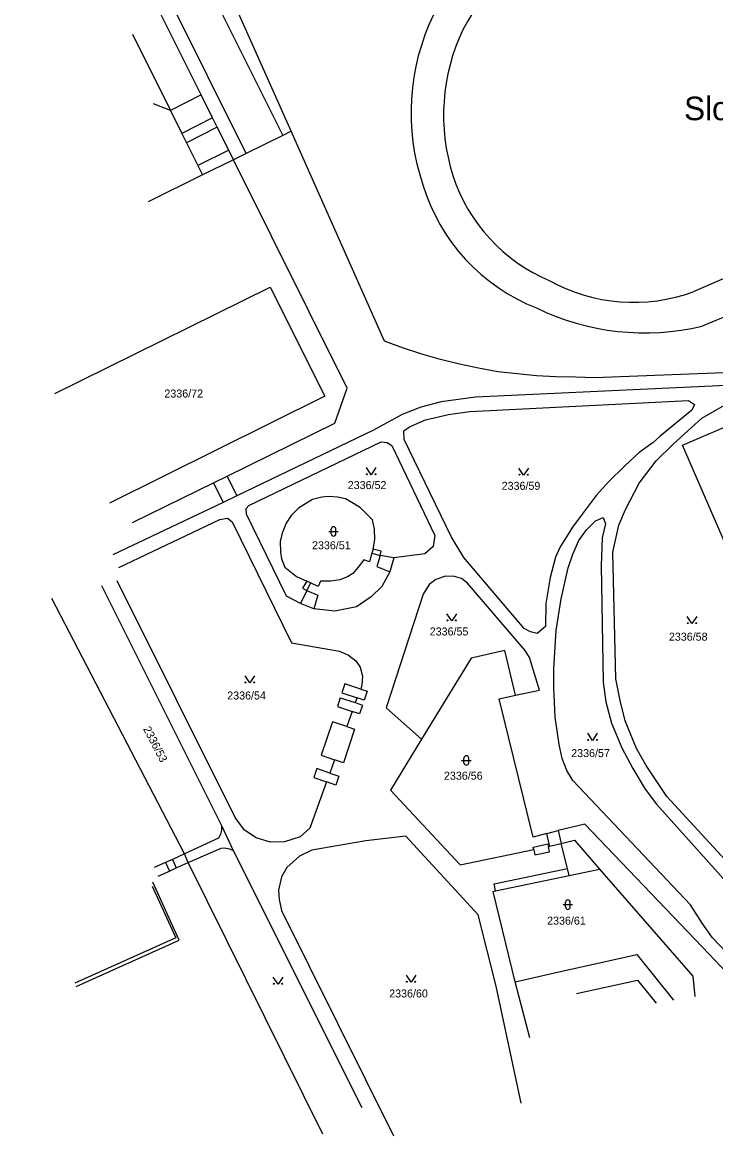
# Model space of a CAD drawing. Extents: x -822293 to -820259, y -1071573 to -1068794.
# Drawn here: x -821067.6 to -820920.3, y -1071364.1 to -1071127.6 of the extents above; entities that cross this region are included whole.
import ezdxf

# ---------------------------------------------------------------- set-up
doc = ezdxf.new("R2010")
doc.units = 0
for name, color, linetype in [('Vrstva 1', 7, 'Continuous'), ('Vrstva 15', 7, 'Continuous'), ('Vrstva 18', 7, 'Continuous'), ('Vrstva 2', 7, 'Continuous'), ('Vrstva 25', 7, 'Continuous'), ('Vrstva 3', 7, 'Continuous'), ('Vrstva 4', 7, 'Continuous')]:
    doc.layers.add(name, color=color, linetype=linetype)

msp = doc.modelspace()

# ---------------------------------------------------------------- linework, layer by layer
at = {"layer": 'Vrstva 1'}
for p, q in [((-821010.48, -1071150.74), (-821030.29, -1071106.24)), ((-821027.17, -1071147.89), (-821029.61, -1071142.98)), ((-821036.15, -1071146.31), (-821033.7, -1071151.22)), ((-821026.2, -1071149.83), (-821027.17, -1071147.89)), ((-821033.7, -1071151.22), (-821032.73, -1071153.16)), ((-821023.75, -1071154.75), (-821026.2, -1071149.83)), ((-821010.48, -1071150.74), (-821012.25, -1071151.61)), ((-820990.69, -1071195.3), (-821010.48, -1071150.74)), ((-821032.73, -1071153.16), (-821030.29, -1071158.03)), ((-821012.25, -1071151.61), (-821020.06, -1071155.46)), ((-821022.74, -1071156.78), (-821023.75, -1071154.75)), ((-821020.06, -1071155.46), (-821022.74, -1071156.78)), ((-821030.29, -1071158.03), (-821029.31, -1071159.98)), ((-821022.74, -1071156.78), (-821029.31, -1071159.98)), ((-820998.6, -1071205.31), (-821022.74, -1071156.78)), ((-821029.31, -1071159.98), (-821040.85, -1071165.71)), ((-821060.69, -1071206.47), (-821014.96, -1071183.85)), ((-821014.96, -1071183.85), (-821003.34, -1071207)), ((-820986.66, -1071196.78), (-820990.69, -1071195.3)), ((-820982.74, -1071198.06), (-820986.66, -1071196.78)), ((-820978.79, -1071199.23), (-820982.74, -1071198.06)), ((-820974.75, -1071200.18), (-820978.79, -1071199.23)), ((-820970.69, -1071201.05), (-820974.75, -1071200.18)), ((-820966.6, -1071201.83), (-820970.69, -1071201.05)), ((-820962.51, -1071202.26), (-820966.6, -1071201.83)), ((-820958.4, -1071202.67), (-820962.51, -1071202.26)), ((-820954.29, -1071202.91), (-820958.4, -1071202.67)), ((-820950.12, -1071203), (-820954.29, -1071202.91)), ((-820946, -1071203.12), (-820950.12, -1071203)), ((-820891.98, -1071201.01), (-820946, -1071203.12)), ((-821001.19, -1071212.77), (-820998.6, -1071205.31)), ((-820893.3, -1071203.6), (-820971.32, -1071207.19)), ((-821003.34, -1071207), (-821049.09, -1071229.74)), ((-820971.32, -1071207.19), (-820978.65, -1071208.22)), ((-820972.51, -1071210.23), (-820926.1, -1071207.9)), ((-820926.1, -1071207.9), (-820924.8, -1071208.8)), ((-820982.97, -1071209.31), (-820986.89, -1071210.89)), ((-820978.65, -1071208.22), (-820982.97, -1071209.31)), ((-820977.04, -1071210.93), (-820972.51, -1071210.23)), ((-820925.4, -1071210), (-820932.1, -1071215.5)), ((-820927.37, -1071217.43), (-820906.4, -1071208.35)), ((-820924.8, -1071208.8), (-820925.4, -1071210)), ((-820923.27, -1071211.68), (-820918.45, -1071208.9)), ((-820986.89, -1071210.89), (-820993.03, -1071214.25)), ((-820985.32, -1071213.51), (-820981.93, -1071212.04)), ((-820981.93, -1071212.04), (-820977.04, -1071210.93)), ((-820929.38, -1071217.23), (-820923.27, -1071211.68)), ((-821024.08, -1071223.99), (-821001.19, -1071212.77)), ((-820993.03, -1071214.25), (-821022.02, -1071228.2)), ((-820986.55, -1071214.4), (-820985.32, -1071213.51)), ((-820986.47, -1071216.23), (-820986.55, -1071214.4)), ((-821019.48, -1071230.25), (-820991.39, -1071216.7)), ((-820991.39, -1071216.7), (-820990.11, -1071216.85)), ((-820990.11, -1071216.85), (-820989.11, -1071217.48)), ((-820976.48, -1071236.8), (-820986.47, -1071216.23)), ((-820933.59, -1071216.82), (-820936.55, -1071218.99)), ((-820932.1, -1071215.5), (-820933.59, -1071216.82)), ((-820932.95, -1071220.72), (-820929.38, -1071217.23)), ((-820903.02, -1071273.66), (-820927.37, -1071217.43)), ((-820989.11, -1071217.48), (-820980, -1071236.62)), ((-820936.55, -1071218.99), (-820939.61, -1071221.78)), ((-820939.61, -1071221.78), (-820943.1, -1071225.2)), ((-820936.6, -1071225.5), (-820932.95, -1071220.72)), ((-821027.01, -1071225.42), (-821024.08, -1071223.99)), ((-821044.19, -1071233.84), (-821027.01, -1071225.42)), ((-820943.1, -1071225.2), (-820945.67, -1071228.1)), ((-820939.5, -1071231.1), (-820936.6, -1071225.5)), ((-821022.02, -1071228.2), (-821024.94, -1071229.6)), ((-821005.93, -1071228.96), (-821007.22, -1071229.71)), ((-821003.99, -1071228.43), (-821005.93, -1071228.96)), ((-821002.57, -1071228.31), (-821003.99, -1071228.43)), ((-821000.67, -1071228.43), (-821002.57, -1071228.31)), ((-820998.93, -1071228.84), (-821000.67, -1071228.43)), ((-820997.23, -1071229.8), (-820998.93, -1071228.84)), ((-820945.67, -1071228.1), (-820948.68, -1071232.05)), ((-821024.94, -1071229.6), (-821048.33, -1071240.68)), ((-821020.06, -1071230.89), (-821019.48, -1071230.25)), ((-821019.99, -1071232.04), (-821020.06, -1071230.89)), ((-821008.91, -1071230.82), (-821010.5, -1071232.37)), ((-821007.22, -1071229.71), (-821008.91, -1071230.82)), ((-820995.76, -1071230.71), (-820997.23, -1071229.8)), ((-820994.37, -1071232.11), (-820995.76, -1071230.71)), ((-820940.87, -1071234.4), (-820939.5, -1071231.1)), ((-821047.08, -1071243.43), (-821025.63, -1071233.18)), ((-821025.63, -1071233.18), (-821024.03, -1071232.92)), ((-821024.03, -1071232.92), (-821023, -1071233.73)), ((-821023, -1071233.73), (-821010.44, -1071259.43)), ((-821011.5, -1071249.52), (-821019.99, -1071232.04)), ((-821011.57, -1071233.97), (-821012.37, -1071236.1)), ((-821010.5, -1071232.37), (-821011.57, -1071233.97)), ((-820993.22, -1071233.29), (-820994.37, -1071232.11)), ((-820992.81, -1071235.26), (-820993.22, -1071233.29)), ((-820948.68, -1071232.05), (-820950.75, -1071234.85)), ((-820947.76, -1071235.4), (-820945.88, -1071233.47)), ((-820945.88, -1071233.47), (-820944.25, -1071232.75)), ((-820944.25, -1071232.75), (-820943.69, -1071234.12)), ((-821012.37, -1071236.1), (-821012.84, -1071237.91)), ((-820992.69, -1071237.45), (-820992.81, -1071235.26)), ((-820950.75, -1071234.85), (-820953.44, -1071239.13)), ((-820949.39, -1071237.7), (-820947.76, -1071235.4)), ((-820943.69, -1071234.12), (-820944.41, -1071237.11)), ((-820942.16, -1071240.13), (-820940.87, -1071234.4)), ((-821012.84, -1071237.91), (-821012.75, -1071240.11)), ((-820993.1, -1071239.54), (-820992.69, -1071237.45)), ((-820980, -1071236.62), (-820980.36, -1071238.92)), ((-820973.8, -1071241.31), (-820976.48, -1071236.8)), ((-820950.64, -1071240.6), (-820949.39, -1071237.7)), ((-820944.41, -1071237.11), (-820944.65, -1071242.99)), ((-821012.75, -1071240.11), (-821012.51, -1071241.55)), ((-820991.36, -1071239.9), (-820993.1, -1071239.54)), ((-820991.57, -1071240.87), (-820991.36, -1071239.9)), ((-820988.69, -1071241.36), (-820991.57, -1071240.87)), ((-820982.07, -1071240.49), (-820988.69, -1071241.36)), ((-820980.36, -1071238.92), (-820982.07, -1071240.49)), ((-820953.44, -1071239.13), (-820954.33, -1071241.2)), ((-820951.63, -1071243.47), (-820950.64, -1071240.6)), ((-820941.51, -1071267.04), (-820942.16, -1071240.13)), ((-821012.51, -1071241.55), (-821011.83, -1071243.35)), ((-821011.83, -1071243.35), (-821009.36, -1071245.3)), ((-820988.69, -1071241.36), (-820989.52, -1071244.29)), ((-820960.99, -1071256.33), (-820973.8, -1071241.31)), ((-820954.33, -1071241.2), (-820955.5, -1071245.5)), ((-820944.65, -1071242.99), (-820944.2, -1071267.75)), ((-821009.36, -1071245.3), (-821007.17, -1071246.28)), ((-820989.52, -1071244.29), (-820991.24, -1071247.47)), ((-820977.73, -1071245.24), (-820979.74, -1071245.92)), ((-820975.77, -1071245.32), (-820977.73, -1071245.24)), ((-820974.3, -1071245.75), (-820975.77, -1071245.32)), ((-820973.02, -1071246.7), (-820974.3, -1071245.75)), ((-820955.5, -1071245.5), (-820956.37, -1071251.03)), ((-820953.14, -1071250.04), (-820951.63, -1071243.47)), ((-821050.76, -1071247.23), (-821025.3, -1071298.24)), ((-821022.4, -1071296.51), (-821047.41, -1071246.21)), ((-821007.17, -1071246.28), (-821008.09, -1071247.8)), ((-821008.09, -1071247.8), (-821007.17, -1071248.31)), ((-820991.24, -1071247.47), (-820993.52, -1071249.63)), ((-820981.2, -1071247.04), (-820982.45, -1071249.04)), ((-820979.74, -1071245.92), (-820981.2, -1071247.04)), ((-820960.81, -1071261), (-820973.02, -1071246.7)), ((-821033.17, -1071304.26), (-821061.35, -1071250.01)), ((-821008.5, -1071251.02), (-821011.5, -1071249.52)), ((-821007.17, -1071248.31), (-821008.5, -1071251.02)), ((-820993.52, -1071249.63), (-820996.63, -1071251.74)), ((-820982.45, -1071249.04), (-820990.29, -1071273.21)), ((-820954.17, -1071256.8), (-820953.14, -1071250.04)), ((-821005.67, -1071252.2), (-821008.5, -1071251.02)), ((-821001.24, -1071252.66), (-821005.67, -1071252.2)), ((-820996.63, -1071251.74), (-821001.24, -1071252.66)), ((-820956.37, -1071251.03), (-820956.47, -1071255.91)), ((-820959.65, -1071257.1), (-820960.99, -1071256.33)), ((-820958.24, -1071257.39), (-820959.65, -1071257.1)), ((-820956.47, -1071255.91), (-820958.24, -1071257.39)), ((-820954.68, -1071264.95), (-820954.17, -1071256.8)), ((-821010.44, -1071259.43), (-821000.25, -1071261.14)), ((-821000.25, -1071261.14), (-820998.29, -1071262.03)), ((-820998.29, -1071262.03), (-820996.78, -1071263.21)), ((-820965.13, -1071261.02), (-820972.25, -1071262.64)), ((-820962.81, -1071270.52), (-820965.13, -1071261.02)), ((-820959.87, -1071262.51), (-820960.81, -1071261)), ((-820996.78, -1071263.21), (-820995.82, -1071264.54)), ((-820995.82, -1071264.54), (-820995.34, -1071266.5)), ((-820972.25, -1071262.64), (-820982.78, -1071279.89)), ((-820957.76, -1071269.44), (-820959.87, -1071262.51)), ((-820995.34, -1071266.5), (-820995.49, -1071268.34)), ((-820954.72, -1071268.93), (-820954.68, -1071264.95)), ((-820940.64, -1071271.67), (-820941.51, -1071267.04)), ((-820995.49, -1071268.34), (-820995.71, -1071269.22)), ((-820995.71, -1071269.22), (-820994.34, -1071269.67)), ((-820962.81, -1071270.52), (-820957.76, -1071269.44)), ((-820954.4, -1071275.22), (-820954.72, -1071268.93)), ((-820944.2, -1071267.75), (-820943.64, -1071271.96)), ((-820996.48, -1071271.08), (-820996.86, -1071272.11)), ((-820994.97, -1071271.57), (-820996.48, -1071271.08)), ((-820994.34, -1071269.67), (-820994.97, -1071271.57)), ((-820966.32, -1071271.27), (-820962.81, -1071270.52)), ((-820959.08, -1071300.71), (-820966.32, -1071271.27)), ((-820939.57, -1071275.97), (-820940.64, -1071271.67)), ((-820997.54, -1071273.99), (-820998.69, -1071277.17)), ((-820995.95, -1071274.51), (-820997.54, -1071273.99)), ((-820996.86, -1071272.11), (-820995.32, -1071272.61)), ((-820995.32, -1071272.61), (-820995.95, -1071274.51)), ((-820990.29, -1071273.21), (-820982.78, -1071279.89)), ((-820943.64, -1071271.96), (-820942.44, -1071276.49)), ((-820953.55, -1071280.98), (-820954.4, -1071275.22)), ((-820942.44, -1071276.49), (-820940.23, -1071281.71)), ((-820937.16, -1071281.87), (-820939.57, -1071275.97)), ((-820997.02, -1071277.73), (-820999.4, -1071284.87)), ((-820998.69, -1071277.17), (-820997.02, -1071277.73)), ((-820982.78, -1071279.89), (-820989.39, -1071290.72)), ((-820952.96, -1071284), (-820953.55, -1071280.98)), ((-820940.23, -1071281.71), (-820937.94, -1071286.09)), ((-820935.1, -1071285.49), (-820937.16, -1071281.87)), ((-821001.25, -1071284.24), (-821002.28, -1071287.07)), ((-820999.4, -1071284.87), (-821001.25, -1071284.24)), ((-820951.97, -1071286.55), (-820952.96, -1071284)), ((-820930.67, -1071292.03), (-820935.1, -1071285.49)), ((-821002.28, -1071287.07), (-821000.35, -1071287.72)), ((-821000.35, -1071287.72), (-821000.98, -1071289.63)), ((-820950.64, -1071288.63), (-820951.97, -1071286.55)), ((-820937.94, -1071286.09), (-820935.29, -1071290.46)), ((-821002.96, -1071288.95), (-821006.51, -1071298.75)), ((-821000.98, -1071289.63), (-821002.96, -1071288.95)), ((-820989.39, -1071290.72), (-820974.59, -1071306.59)), ((-820925.65, -1071315.06), (-820950.64, -1071288.63)), ((-820935.29, -1071290.46), (-820932.9, -1071293.66)), ((-820912.55, -1071311.81), (-820930.67, -1071292.03)), ((-820932.9, -1071293.66), (-820914.14, -1071314.59)), ((-821020.39, -1071299.2), (-821022.4, -1071296.51)), ((-821025.53, -1071300.14), (-821025.9, -1071300.87)), ((-821025.31, -1071299.16), (-821025.53, -1071300.14)), ((-821025.3, -1071298.24), (-821025.31, -1071299.16)), ((-821025.3, -1071298.24), (-821022.8, -1071303.49)), ((-821017.89, -1071300.81), (-821020.39, -1071299.2)), ((-821006.51, -1071298.75), (-821008.56, -1071300.63)), ((-820956.15, -1071299.94), (-820959.08, -1071300.71)), ((-820955.72, -1071302.07), (-820956.15, -1071299.94)), ((-820948.14, -1071297.93), (-820953.75, -1071299.28)), ((-820953.75, -1071299.28), (-820953.11, -1071302.04)), ((-820923.16, -1071324), (-820948.14, -1071297.93)), ((-821025.9, -1071300.87), (-821033.17, -1071304.26)), ((-821014.91, -1071301.78), (-821017.89, -1071300.81)), ((-821011.89, -1071301.66), (-821014.91, -1071301.78)), ((-821008.56, -1071300.63), (-821011.89, -1071301.66)), ((-820994.65, -1071301.46), (-821006.08, -1071303.45)), ((-820986.14, -1071300.48), (-820994.65, -1071301.46)), ((-820970.77, -1071317.2), (-820986.14, -1071300.48)), ((-820955.85, -1071302.64), (-820955.62, -1071302.59)), ((-820955.62, -1071302.59), (-820955.72, -1071302.07)), ((-820953.11, -1071302.04), (-820950.32, -1071301.33)), ((-820951.82, -1071307.37), (-820953.11, -1071302.04)), ((-820950.32, -1071301.33), (-820944.97, -1071307.48)), ((-821032.35, -1071306.08), (-821025.36, -1071303.04)), ((-821025.36, -1071303.04), (-821024.64, -1071302.96)), ((-821024.64, -1071302.96), (-821023.55, -1071303.16)), ((-821023.55, -1071303.16), (-821022.8, -1071303.49)), ((-821022.8, -1071303.49), (-820995.49, -1071358.1)), ((-821008.73, -1071304.73), (-821011.39, -1071307.11)), ((-821006.08, -1071303.45), (-821008.73, -1071304.73)), ((-820974.59, -1071306.59), (-820958.96, -1071303.3)), ((-820958.96, -1071303.3), (-820958.72, -1071304.44)), ((-820958.72, -1071304.44), (-820955.61, -1071303.78)), ((-820955.61, -1071303.78), (-820955.85, -1071302.64)), ((-821003.74, -1071363.8), (-821032.35, -1071306.08)), ((-821011.39, -1071307.11), (-821012.56, -1071309.11)), ((-821012.56, -1071309.11), (-821013.2, -1071311.91)), ((-820967.07, -1071312.11), (-820951.46, -1071308.8)), ((-820951.46, -1071308.8), (-820951.82, -1071307.37)), ((-820944.97, -1071307.48), (-820925.14, -1071330.2)), ((-821034.28, -1071322.58), (-821039.84, -1071310.23)), ((-821013.2, -1071311.91), (-821013.07, -1071313.92)), ((-821013.07, -1071313.92), (-821012.54, -1071316.24)), ((-820967.58, -1071312.22), (-820967.07, -1071312.11)), ((-820962.92, -1071331.39), (-820967.58, -1071312.22)), ((-821012.54, -1071316.24), (-820988.78, -1071364.11)), ((-820923.22, -1071318.94), (-820925.65, -1071315.06)), ((-820966.98, -1071332.31), (-820970.77, -1071317.2)), ((-820921.01, -1071322.06), (-820923.22, -1071318.94)), ((-821056.12, -1071332.42), (-821034.28, -1071322.58)), ((-820904.5, -1071339.5), (-820921.01, -1071322.06)), ((-820954.56, -1071329.5), (-820937.08, -1071325.59)), ((-820937.08, -1071325.59), (-820929.29, -1071335.31)), ((-820897.48, -1071351.2), (-820923.16, -1071324)), ((-820962.92, -1071331.39), (-820954.56, -1071329.5)), ((-820925.14, -1071330.2), (-820924.75, -1071334.52)), ((-820961.63, -1071357.21), (-820966.98, -1071332.31)), ((-820959.81, -1071343.33), (-820962.92, -1071331.39)), ((-820949.87, -1071333.88), (-820936.96, -1071331.06)), ((-820936.96, -1071331.06), (-820932.97, -1071335.97))]:
    msp.add_line(p, q, dxfattribs=at)
at = {"layer": 'Vrstva 2'}
for p, q in [((-821029.61, -1071142.98), (-821067.6, -1071066.7)), ((-821044.21, -1071130.13), (-821036.15, -1071146.31))]:
    msp.add_line(p, q, dxfattribs=at)
at = {"layer": 'Vrstva 25'}
for p, q in [((-821002.49, -1071235.73), (-821000.49, -1071235.73)), ((-821001.99, -1071236.23), (-821001.99, -1071235.23)), ((-821000.99, -1071236.23), (-821000.99, -1071235.23)), ((-820974.28, -1071284.381), (-820972.28, -1071284.381)), ((-820973.78, -1071284.881), (-820973.78, -1071283.881)), ((-820972.78, -1071284.881), (-820972.78, -1071283.881)), ((-820952.72, -1071315.02), (-820950.72, -1071315.02)), ((-820952.22, -1071315.52), (-820952.22, -1071314.52)), ((-820951.22, -1071315.52), (-820951.22, -1071314.52))]:
    msp.add_line(p, q, dxfattribs=at)
for points in [[(-820992.5, -1071222.19), (-820993.5, -1071223.69), (-820994.5, -1071222.19)], [(-820960.11, -1071222.28), (-820961.11, -1071223.78), (-820962.11, -1071222.28)], [(-820975.39, -1071253.23), (-820976.39, -1071254.73), (-820977.39, -1071253.23)], [(-820924.35, -1071253.83), (-820925.35, -1071255.33), (-820926.35, -1071253.83)], [(-821018.26, -1071266.4), (-821019.26, -1071267.9), (-821020.26, -1071266.4)], [(-820945.48, -1071278.62), (-820946.48, -1071280.12), (-820947.48, -1071278.62)], [(-821012.28, -1071330.41), (-821013.28, -1071331.91), (-821014.28, -1071330.41)], [(-820984.02, -1071329.99), (-820985.02, -1071331.49), (-820986.02, -1071329.99)]]:
    msp.add_lwpolyline(points, dxfattribs=at)
for centre in [(-820994.4, -1071223.59), (-820992.6, -1071223.59), (-820962.01, -1071223.68), (-820960.21, -1071223.68), (-820977.29, -1071254.63), (-820975.49, -1071254.63), (-820926.25, -1071255.23), (-820924.45, -1071255.23), (-821020.16, -1071267.8), (-821018.36, -1071267.8), (-820947.38, -1071280.02), (-820945.58, -1071280.02), (-821014.18, -1071331.81), (-821012.38, -1071331.81), (-820985.92, -1071331.39), (-820984.12, -1071331.39)]:
    msp.add_circle(centre, 0.1, dxfattribs=at)
for centre, start, end in [((-821001.49, -1071235.23), 0, 180), ((-821001.49, -1071236.23), 180, 0), ((-820973.28, -1071283.881), 0, 180), ((-820973.28, -1071284.881), 180, 0), ((-820951.72, -1071314.52), 0, 180), ((-820951.72, -1071315.52), 180, 0)]:
    msp.add_arc(centre, 0.5, start, end, dxfattribs=at)
at = {"layer": 'Vrstva 3'}
for p, q in [((-821029.61, -1071142.98), (-821036.15, -1071146.31)), ((-821040, -1071311.12), (-821035.01, -1071322.08)), ((-821035.01, -1071322.08), (-821056.43, -1071331.73))]:
    msp.add_line(p, q, dxfattribs=at)
at = {"layer": 'Vrstva 4'}
for p, q in [((-821020.06, -1071155.46), (-821064.15, -1071066.88)), ((-821028.99, -1071118.14), (-821012.25, -1071151.61)), ((-821036.15, -1071146.31), (-821039.75, -1071144.92)), ((-821027.17, -1071147.89), (-821033.7, -1071151.22)), ((-821026.2, -1071149.83), (-821032.73, -1071153.16)), ((-821023.75, -1071154.75), (-821030.29, -1071158.03)), ((-820910.34, -1071178.44), (-820925.08, -1071184.83)), ((-820906.86, -1071185.41), (-820923.22, -1071192.13)), ((-821024.08, -1071223.99), (-821022.02, -1071228.2)), ((-821027.01, -1071225.42), (-821024.94, -1071229.6)), ((-820993.34, -1071240.35), (-820993.87, -1071242.17)), ((-820993.1, -1071239.54), (-820993.34, -1071240.35)), ((-820993.34, -1071240.35), (-820991.57, -1071240.87)), ((-820991.57, -1071240.87), (-820992.3, -1071243.2)), ((-820996.23, -1071243.33), (-820997.42, -1071244.71)), ((-820995.05, -1071241.79), (-820996.23, -1071243.33)), ((-820993.87, -1071242.17), (-820995.05, -1071241.79)), ((-820992.3, -1071243.2), (-820989.52, -1071244.29)), ((-820998.54, -1071245.35), (-821000.17, -1071246.05)), ((-820997.42, -1071244.71), (-820998.54, -1071245.35)), ((-821006.37, -1071246.67), (-821007.17, -1071246.28)), ((-821006.37, -1071246.67), (-821007.17, -1071248.31)), ((-821004.74, -1071247.47), (-821006.37, -1071246.67)), ((-821004.27, -1071246.29), (-821004.74, -1071247.47)), ((-821002.05, -1071246.27), (-821004.27, -1071246.29)), ((-821000.17, -1071246.05), (-821002.05, -1071246.27)), ((-821007.17, -1071248.31), (-821004.79, -1071249.28)), ((-821004.79, -1071249.28), (-821005.67, -1071252.2)), ((-820999.07, -1071268.1), (-820999.71, -1071270.02)), ((-820995.71, -1071269.22), (-820999.07, -1071268.1)), ((-821000.05, -1071271.07), (-821000.68, -1071272.96)), ((-821000.05, -1071271.07), (-820996.86, -1071272.11)), ((-820999.71, -1071270.02), (-820996.48, -1071271.08)), ((-821000.68, -1071272.96), (-820997.54, -1071273.99)), ((-821001.74, -1071276.16), (-821004.1, -1071283.27)), ((-820998.69, -1071277.17), (-821001.74, -1071276.16)), ((-821004.1, -1071283.27), (-821001.25, -1071284.24)), ((-821005.05, -1071286.13), (-821005.67, -1071288.02)), ((-821005.67, -1071288.02), (-821002.96, -1071288.95)), ((-821002.28, -1071287.07), (-821005.05, -1071286.13)), ((-820956.15, -1071299.94), (-820953.75, -1071299.28)), ((-820959.07, -1071302.78), (-820955.96, -1071302.12)), ((-820955.96, -1071302.12), (-820955.85, -1071302.64)), ((-820955.62, -1071302.59), (-820953.11, -1071302.04)), ((-821033.17, -1071304.26), (-821035.72, -1071305.41)), ((-821032.35, -1071306.08), (-821033.17, -1071304.26)), ((-820958.96, -1071303.3), (-820959.07, -1071302.78)), ((-821037.15, -1071306.06), (-821039.59, -1071307.16)), ((-821035.72, -1071305.41), (-821037.15, -1071306.06)), ((-821037.15, -1071306.06), (-821036.33, -1071307.88)), ((-821036.33, -1071307.88), (-821034.9, -1071307.23)), ((-821035.72, -1071305.41), (-821034.9, -1071307.23)), ((-821034.9, -1071307.23), (-821032.35, -1071306.08)), ((-821038.77, -1071308.98), (-821036.33, -1071307.88)), ((-820967.36, -1071310.63), (-820951.82, -1071307.37)), ((-820951.46, -1071308.8), (-820944.97, -1071307.48)), ((-820967.07, -1071312.11), (-820967.36, -1071310.63))]:
    msp.add_line(p, q, dxfattribs=at)
for centre, radius, start, end in [((-820927.829, -1071153.612), 52.25, 116.86415, 152.08505), ((-820937.484, -1071146.78), 47.552, 154.04685, 198.83204), ((-820935.726, -1071147.363), 42.387, 154.55281, 197.50219), ((-820941.436, -1071148.832), 36.5, 197.99875, 247.20051), ((-820943.467, -1071150.315), 40.773, 196.84524, 248.57536), ((-820937.756, -1071150.248), 36.832, 241.05809, 290.13013), ((-820935.382, -1071140.966), 52.59, 244.09166, 283.37115)]:
    msp.add_arc(centre, radius, start, end, dxfattribs=at)

# ---------------------------------------------------------------- texts
at = {"layer": 'Vrstva 15'}
msp.add_text('Slovany', height=5, dxfattribs=at).set_placement((-820927.032, -1071148.38))
at = {"layer": 'Vrstva 18'}
for s, p in [('2336/72', (-821037.414, -1071207.29)), ('2336/52', (-820998.471, -1071226.74)), ('2336/59', (-820965.776, -1071226.9)), ('2336/51', (-821006.059, -1071239.53)), ('2336/55', (-820981.058, -1071257.84)), ('2336/58', (-820930.26, -1071258.95)), ('2336/54', (-821024.066, -1071271.44)), ('2336/57', (-820951.01, -1071283.68)), ('2336/56', (-820978.036, -1071288.48)), ('2336/61', (-820956.128, -1071319.27)), ('2336/60', (-820989.668, -1071334.74))]:
    msp.add_text(s, height=1.7, dxfattribs=at).set_placement(p)
msp.add_text('2336/53', height=1.7, rotation=297.44946, dxfattribs=at).set_placement((-821041.978, -1071277.675))

doc.saveas('drawing.dxf')
